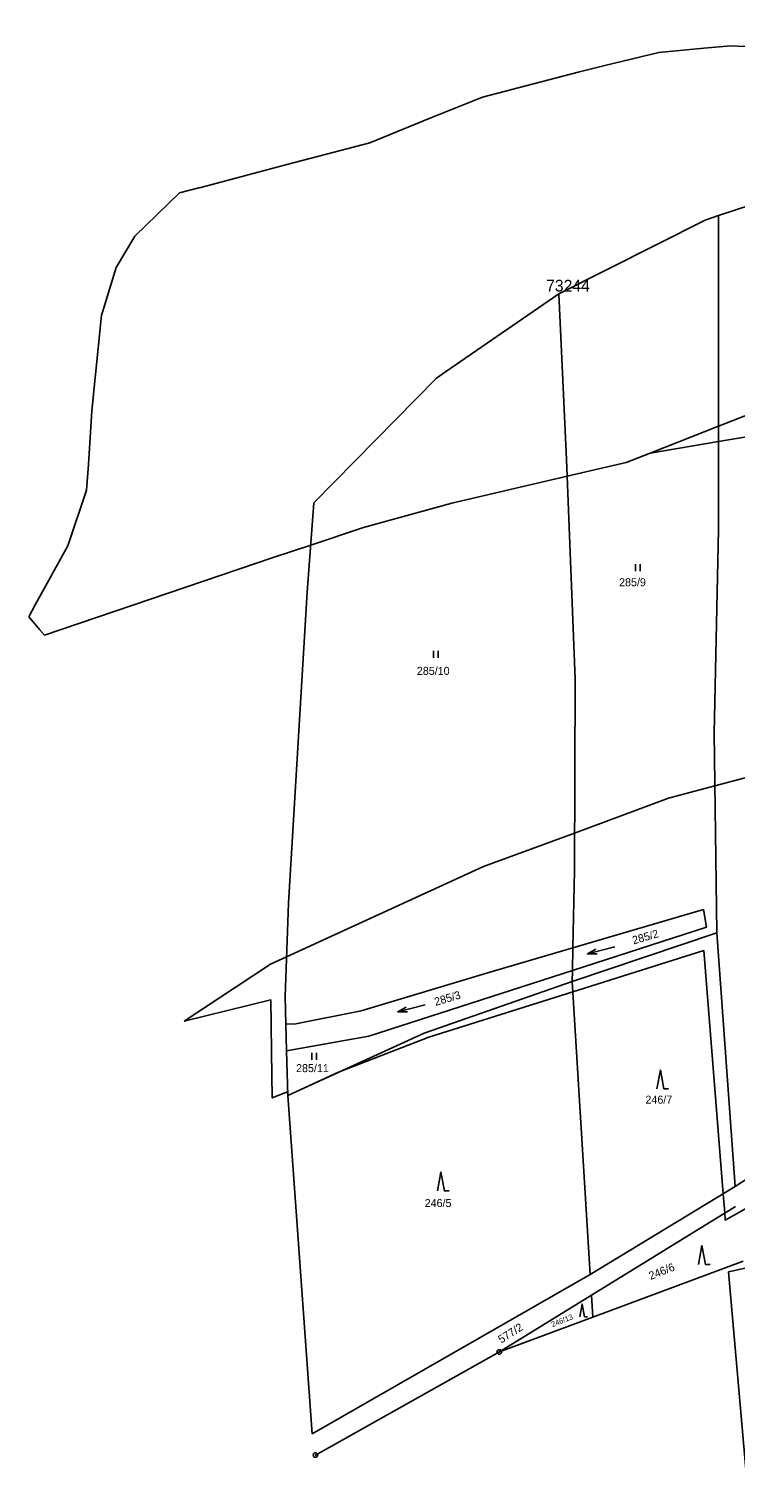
# Model space of a CAD drawing. Extents: x -760978 to -760029, y -1177282 to -1176414.
# Drawn here: x -760977.7 to -760827.5, y -1176736.5 to -1176431.5 of the extents above; entities that cross this region are included whole.
import ezdxf

# ---------------------------------------------------------------- set-up
doc = ezdxf.new("R2010")
doc.units = 0
for name, color, linetype in [('1', 7, 'Continuous'), ('11', 7, 'Continuous'), ('2', 7, 'Continuous'), ('3', 7, 'Continuous'), ('8', 7, 'Continuous')]:
    doc.layers.add(name, color=color, linetype=linetype)

msp = doc.modelspace()

# ---------------------------------------------------------------- linework, layer by layer
at = {"layer": '1'}
for p, q in [((-760831.02, -1176471.17), (-760802.06, -1176461.5)), ((-760864.97, -1176487.79), (-760833.9, -1176472.13)), ((-760833.9, -1176472.13), (-760831.02, -1176471.17)), ((-760831.02, -1176537.94), (-760831.02, -1176471.17)), ((-760889.09, -1176504.34), (-760864.97, -1176487.79)), ((-760864.97, -1176487.79), (-760863.35, -1176523.01)), ((-760917.06, -1176532.16), (-760891.02, -1176505.67)), ((-760891.02, -1176505.67), (-760889.09, -1176504.34)), ((-760863.35, -1176523.01), (-760861.5, -1176569.59)), ((-760918.48, -1176551.14), (-760917.06, -1176532.16)), ((-760831.94, -1176581.13), (-760831.02, -1176537.94)), ((-760918.48, -1176551.14), (-760922.44, -1176617.27)), ((-760861.5, -1176569.59), (-760861.68, -1176610.29)), ((-760831.37, -1176623.54), (-760831.94, -1176581.13)), ((-760861.68, -1176610.29), (-760861.99, -1176626.76)), ((-760922.44, -1176617.27), (-760923.16, -1176637.04)), ((-760861.99, -1176626.76), (-760834.23, -1176618.62)), ((-760834.23, -1176618.62), (-760833.56, -1176622.37)), ((-760862.13, -1176633.91), (-760831.37, -1176623.54)), ((-760833.56, -1176622.37), (-760862.08, -1176631.55)), ((-760831.37, -1176623.54), (-760827.49, -1176677.42)), ((-760879.85, -1176632), (-760861.99, -1176626.76)), ((-760861.99, -1176626.76), (-760862.08, -1176631.55)), ((-760907, -1176640.14), (-760879.85, -1176632)), ((-760862.08, -1176631.55), (-760905.38, -1176645.48)), ((-760893.63, -1176644.84), (-760862.13, -1176633.91)), ((-760862.08, -1176631.55), (-760862.13, -1176633.91)), ((-760858.34, -1176696.15), (-760862.13, -1176633.91)), ((-760923.16, -1176637.04), (-760923.01, -1176642.97)), ((-760920.89, -1176642.88), (-760907, -1176640.14)), ((-760923.01, -1176642.97), (-760920.89, -1176642.88)), ((-760923.01, -1176642.97), (-760922.86, -1176648.63)), ((-760905.38, -1176645.48), (-760922.86, -1176648.63)), ((-760922.62, -1176658.08), (-760893.63, -1176644.84)), ((-760922.86, -1176648.63), (-760922.62, -1176658.08)), ((-760917.4, -1176730.01), (-760922.62, -1176658.08)), ((-760827.49, -1176677.42), (-760797.38, -1176657.89)), ((-760858.34, -1176696.15), (-760827.49, -1176677.42)), ((-760827.45, -1176681.66), (-760858.05, -1176700.53)), ((-760857.74, -1176705.18), (-760825.82, -1176693.28)), ((-760917.4, -1176730.01), (-760858.34, -1176696.15)), ((-760858.05, -1176700.53), (-760877.62, -1176712.59)), ((-760858.05, -1176700.53), (-760857.74, -1176705.18)), ((-760877.62, -1176712.59), (-760857.74, -1176705.18)), ((-760877.62, -1176712.59), (-760916.73, -1176734.5))]:
    msp.add_line(p, q, dxfattribs=at)
at = {"layer": '11'}
for points in [[(-760614.95, -1176431.46), (-760618.87, -1176437.32), (-760622.12, -1176440.58), (-760623.19, -1176441.66), (-760629.23, -1176447.72), (-760642.12, -1176457.4), (-760646.84, -1176460.94), (-760664.41, -1176470.72), (-760670.4, -1176474.06), (-760676.61, -1176477.78), (-760677.25, -1176478.16), (-760685.46, -1176481.23), (-760716.1, -1176492.68), (-760717.08, -1176493.01), (-760736.58, -1176499.5), (-760744.89, -1176501.69), (-760773.08, -1176509.13), (-760777.07, -1176510.18), (-760800.34, -1176514.06), (-760831.02, -1176519.18), (-760845.57, -1176521.61)], [(-760804.1, -1176436.23), (-760828.44, -1176435.09), (-760834.15, -1176435.62), (-760843.74, -1176436.5), (-760855.24, -1176439.25), (-760860.87, -1176440.7), (-760881.23, -1176445.97), (-760892.2, -1176450.42), (-760905.16, -1176455.68), (-760922.51, -1176460.26), (-760941.1, -1176465.16), (-760941.53, -1176465.28), (-760945.64, -1176466.36), (-760955.13, -1176475.5), (-760959.06, -1176482.21), (-760961.99, -1176491.66), (-760962.19, -1176492.32), (-760964.23, -1176512.61), (-760964.99, -1176524.06), (-760965.36, -1176529.53), (-760969.37, -1176541.32), (-760976.28, -1176553.86), (-760977.68, -1176556.41)], [(-760845.57, -1176521.61), (-760831.02, -1176515.92), (-760800.5, -1176504), (-760799.02, -1176503.42), (-760776.36, -1176493.25), (-760773.74, -1176491.37), (-760761.34, -1176482.52), (-760744.63, -1176469.66), (-760726.95, -1176456.05), (-760725.22, -1176454.9), (-760716.49, -1176449.05), (-760712.8, -1176446.58)], [(-760845.57, -1176521.61), (-760850.7, -1176523.63), (-760863.21, -1176526.54), (-760887.75, -1176532.25), (-760906.51, -1176537.41), (-760917.73, -1176541.16), (-760925.71, -1176543.83)], [(-760925.71, -1176543.83), (-760974.35, -1176560.29), (-760975.39, -1176559.08), (-760976.04, -1176558.32), (-760977.68, -1176556.41)], [(-760944.63, -1176642.33), (-760926.29, -1176630.23), (-760922.85, -1176628.66), (-760880.97, -1176609.48), (-760861.64, -1176602.34), (-760841.69, -1176594.96), (-760831.79, -1176592.34), (-760817.83, -1176588.63), (-760799.04, -1176585.67), (-760776.99, -1176582.19), (-760770.09, -1176581.88), (-760741.47, -1176580.56), (-760724.76, -1176579.78), (-760712.22, -1176579.54), (-760702.69, -1176579.35), (-760677.7, -1176577.38), (-760675.27, -1176577.18), (-760662.85, -1176576.2), (-760659.35, -1176575.93), (-760650.06, -1176573.82), (-760631.67, -1176569.67), (-760618.86, -1176565.92), (-760593.94, -1176558.62)], [(-760944.63, -1176642.33), (-760926.19, -1176637.79), (-760926.12, -1176643.12), (-760926.04, -1176648.86), (-760925.91, -1176658.62), (-760922.64, -1176657.35), (-760922.62, -1176658.08), (-760911.82, -1176653.15), (-760892.6, -1176645.69), (-760862, -1176636.06), (-760834.17, -1176627.3), (-760830.05, -1176678.97), (-760829.72, -1176683.06), (-760829.6, -1176684.57), (-760827.23, -1176683.23), (-760799.19, -1176667.34), (-760796.13, -1176685.69), (-760795.71, -1176688.17), (-760828.93, -1176695.59), (-760825.16, -1176738.31)]]:
    msp.add_lwpolyline(points, dxfattribs=at)
at = {"layer": '3'}
for p, q in [((-760848.7, -1176545.23), (-760848.7, -1176546.73)), ((-760847.7, -1176546.73), (-760847.7, -1176545.23)), ((-760891.61, -1176563.65), (-760891.61, -1176565.15)), ((-760890.61, -1176565.15), (-760890.61, -1176563.65)), ((-760853.11, -1176626.49), (-760858.91, -1176628.03)), ((-760893.42, -1176638.86), (-760899.24, -1176640.3)), ((-760917.51, -1176649.04), (-760917.51, -1176650.54)), ((-760916.51, -1176650.54), (-760916.51, -1176649.04))]:
    msp.add_line(p, q, dxfattribs=at)
for points in [[(-760856.85, -1176628), (-760858.91, -1176628.03), (-760857.1, -1176627.03)], [(-760897.18, -1176640.31), (-760899.24, -1176640.3), (-760897.42, -1176639.34)], [(-760844.14, -1176656.69), (-760843.39, -1176652.69), (-760842.64, -1176656.69), (-760841.64, -1176656.69)], [(-760890.79, -1176678.36), (-760890.04, -1176674.36), (-760889.29, -1176678.36), (-760888.29, -1176678.36)], [(-760835.3, -1176693.99), (-760834.55, -1176689.99), (-760833.8, -1176693.99), (-760832.8, -1176693.99)], [(-760860.53, -1176705.11), (-760860.03, -1176702.43), (-760859.53, -1176705.11), (-760858.86, -1176705.11)]]:
    msp.add_lwpolyline(points, dxfattribs=at)
at = {"layer": '8'}
for p, q in [((-760877.74, -1176712.59), (-760877.5, -1176712.59)), ((-760916.85, -1176734.5), (-760916.61, -1176734.5))]:
    msp.add_line(p, q, dxfattribs=at)
for points in [[(-760877.47, -1176712.11), (-760877.22, -1176712.29), (-760877.12, -1176712.58), (-760877.22, -1176712.87), (-760877.47, -1176713.05), (-760877.78, -1176713.05), (-760878.03, -1176712.87), (-760878.13, -1176712.58), (-760878.03, -1176712.29), (-760877.78, -1176712.11)], [(-760916.58, -1176734.02), (-760916.33, -1176734.2), (-760916.23, -1176734.49), (-760916.33, -1176734.78), (-760916.58, -1176734.96), (-760916.89, -1176734.96), (-760917.14, -1176734.78), (-760917.24, -1176734.49), (-760917.14, -1176734.2), (-760916.89, -1176734.02)]]:
    msp.add_lwpolyline(points, close=True, dxfattribs=at)

# ---------------------------------------------------------------- texts
at = {"layer": '11'}
msp.add_text('73244', height=2.5, dxfattribs=at).set_placement((-760867.69, -1176487.3))
at = {"layer": '2'}
for s, p in [('285/9', (-760852.17, -1176549.91)), ('285/10', (-760895.16, -1176568.74)), ('285/11', (-760920.84, -1176653.14)), ('246/7', (-760846.56, -1176659.83)), ('246/5', (-760893.5, -1176681.8))]:
    msp.add_text(s, height=1.7, dxfattribs=at).set_placement(p)
for s, height, rotation, p in [('285/2', 1.7, 16.1574, (-760849.08, -1176626.01)), ('285/3', 1.7, 16.3293, (-760891.16, -1176639.06)), ('246/6', 1.7, 21.7151, (-760845.46, -1176697.3)), ('577/2', 1.7, 32.4867, (-760877.22, -1176710.83)), ('246/13', 1.14, 21.6005, (-760866.34, -1176707.34))]:
    msp.add_text(s, height=height, rotation=rotation, dxfattribs=at).set_placement(p)

doc.saveas('drawing.dxf')
